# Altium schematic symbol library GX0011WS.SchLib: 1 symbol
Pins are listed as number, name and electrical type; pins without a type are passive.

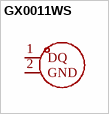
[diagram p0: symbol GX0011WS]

## GX0011WS
designator U?  (value not drawn)
footprint TO-92S-2_L4.0-W1.5-P1.27-L
pins: 1 DQ, 2 GND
